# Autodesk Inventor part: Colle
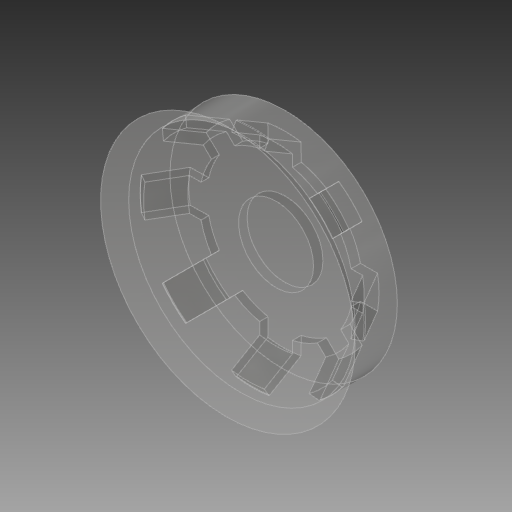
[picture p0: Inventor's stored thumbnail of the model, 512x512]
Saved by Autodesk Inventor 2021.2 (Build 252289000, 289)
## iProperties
Created: 2018-06
Part Number: Colle
Material: Polycarbonate, transparent
Document SubType Name: Modeling
Designer: Fabian Perrée
Density: 1.2 g/cm^3
Appearance: Polycarbonate - Transparent
Mass: 0.374274 g
Surface Area: 4.66707 cm^2
Volume: 0.311895 cm^3
Author: Fabian Perrée
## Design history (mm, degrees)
node "Plan de construction1"
  node "Axe de construction1"
sketch "Esquisse1"
  geometry: L1 (-3, -6)-(-3, 6) reference; L2 (0, -6.75)-(0, 6.75) reference; L3 (-0.75, 6)-(-0.75, -6) reference; L4 (-3, 6)-(-0.75, 6); L5 (0, 6.75)-(-0.75, 6); L6 (0, 6.75)-(0, 0.032); L7 (0, 0.032)-(-3, 0); L8 (-3, 6)-(-3, 0)
  constraints: 10 end point, 2 collinear, 1 horizontal, 1 midpoint
revolve "Révolution1" sketch "Esquisse1" stored, may be unused: angle "d1" = 90 deg
derived "Bouchon.ipt"
feature "Déplacer des corps2"
feature "Déplacer des corps1"
feature "Déplacer des corps3"
feature "Combiner1"
  node "Solide2"
node "Solide1"
node "Référence1"
node "Référence2"
node "Référence3"
feature "Solide1::Bouchon.ipt" dims "d2" = 10
tag "FonctionRepérage1"
other parameters: "d0" = 0, "d3" = 0, "d4" = -24, "d5" = 0, "d6" = 90 deg, "d7" = 0, "d8" = 0, "d9" = -3
